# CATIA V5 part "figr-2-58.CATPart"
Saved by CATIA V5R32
Part number: Part1
Bounding box of the stored display mesh (mm): x 0 to 40, y -49.816 to 150, z -49.907 to 49.907
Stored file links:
  D:\PROJECTS\Project 2022\CATIA V5 6R 2022\Resources\Part Files\c02_catia_v5_6r2022_prt\figr-2-58.CATPart
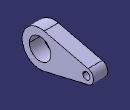
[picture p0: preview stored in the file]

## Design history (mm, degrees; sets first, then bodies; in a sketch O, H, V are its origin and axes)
Body1 (main body)
  Sketch1 on yz-plane, origin (0, 0, 0), H (0, 1, 0), V (0, 0, 1)
    arc A1 centre (0, 0) radius 50 from (11.5385, 48.6504) to (11.5385, -48.6504) ccw
    arc A2 centre (130, 0) radius 20 from (134.6154, -19.4602) to (134.6154, 19.4602) ccw
    point P1 (130, 0)
    line L1 (134.6154, 19.4602) -> (11.5385, 48.6504)
    line L2 (134.6154, -19.4602) -> (11.5385, -48.6504)
    circle A3 centre (0, 0) radius 30
    circle A4 centre (130, 0) radius 10
    point P6 (120, 0)
    coincidence: P1 H, A4 P6, P6 H
    tangency: L1 A2, L1 A1, L2 A2, L2 A1
  Pad1: profile Sketch1, direction (1, 0, 0), length 40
